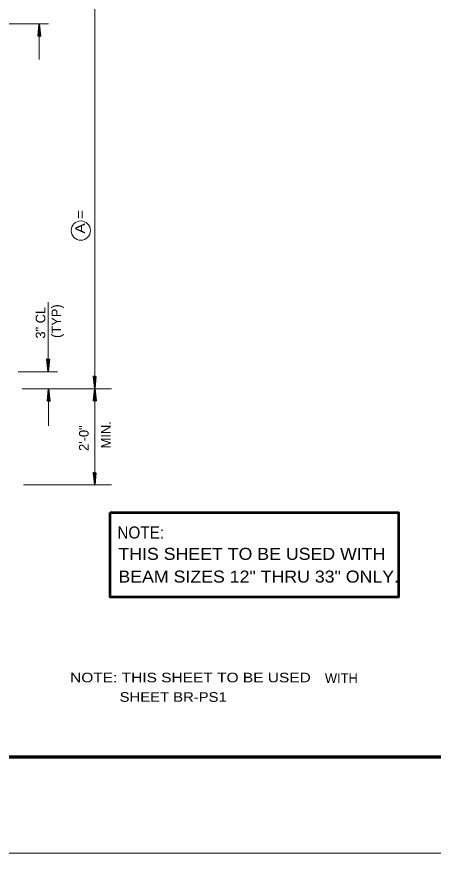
# Model space of a CAD drawing. Extents: x 14.14 to 17.34, y -1.61 to 0.38.
# Drawn here: x 15.839 to 16.199, y -1.605 to -0.881 of the extents above; entities that cross this region are included whole.
import ezdxf

# ---------------------------------------------------------------- set-up
doc = ezdxf.new("R2010")
doc.units = 0
doc.header["$LTSCALE"] = 0.0033
doc.layers.add('1', color=7, linetype='Continuous', lineweight=40)

msp = doc.modelspace()

# ---------------------------------------------------------------- linework, layer by layer
at = {"layer": '1', "lineweight": 13}
for p, q in [((15.906667, -1.285167), (15.906667, -0.869417)), ((15.743333, -0.887), (15.86675, -0.887)), ((15.85875, -0.917667), (15.85875, -0.896833)), ((15.866583, -1.18125), (15.866583, -1.127917)), ((15.840583, -1.188), (15.8745, -1.188)), ((15.844083, -1.202667), (15.92125, -1.202667)), ((15.866833, -1.234833), (15.866833, -1.214)), ((15.845083, -1.286), (15.92125, -1.286)), ((17.339333, -1.60475), (14.142583, -1.60475))]:
    msp.add_line(p, q, dxfattribs=at)
at = {"layer": '1', "lineweight": 35}
for p, q in [((15.85775, -0.89725), (15.858667, -0.889417)), ((15.85775, -0.89725), (15.858667, -0.889417)), ((15.857833, -0.89725), (15.858667, -0.889417)), ((15.857917, -0.89725), (15.85875, -0.889417)), ((15.857917, -0.89725), (15.858917, -0.889417)), ((15.859417, -0.897333), (15.858667, -0.89)), ((15.85875, -0.8975), (15.85875, -0.886917)), ((15.859583, -0.89725), (15.85875, -0.889917)), ((15.859667, -0.89725), (15.858917, -0.889917)), ((15.859833, -0.89725), (15.859, -0.889917)), ((15.865333, -1.177333), (15.866167, -1.184667)), ((15.8655, -1.177333), (15.86625, -1.184667)), ((15.865583, -1.177333), (15.866417, -1.184667)), ((15.86575, -1.17725), (15.8665, -1.184583)), ((15.86725, -1.177333), (15.86625, -1.185167)), ((15.866417, -1.177083), (15.866417, -1.187667)), ((15.86725, -1.177333), (15.866417, -1.185167)), ((15.867417, -1.177333), (15.8665, -1.185167)), ((15.867417, -1.177333), (15.8665, -1.185167)), ((15.867333, -1.177333), (15.8665, -1.185167)), ((15.905583, -1.19225), (15.906417, -1.199583)), ((15.90575, -1.19225), (15.9065, -1.199583)), ((15.905833, -1.19225), (15.906667, -1.199583)), ((15.906, -1.192167), (15.90675, -1.1995)), ((15.9075, -1.19225), (15.9065, -1.200083)), ((15.906667, -1.192), (15.906667, -1.202583)), ((15.9075, -1.19225), (15.906667, -1.200083)), ((15.907667, -1.19225), (15.90675, -1.200083)), ((15.907667, -1.19225), (15.90675, -1.200083)), ((15.907583, -1.19225), (15.90675, -1.200083)), ((15.865833, -1.213167), (15.86675, -1.205333)), ((15.865833, -1.213167), (15.86675, -1.205333)), ((15.865917, -1.213167), (15.86675, -1.205333)), ((15.866, -1.213167), (15.866833, -1.205333)), ((15.866, -1.213167), (15.867, -1.205333)), ((15.8675, -1.21325), (15.86675, -1.205917)), ((15.866833, -1.213417), (15.866833, -1.202833)), ((15.867667, -1.213167), (15.866833, -1.205833)), ((15.86775, -1.213167), (15.867, -1.205833)), ((15.867917, -1.213167), (15.867083, -1.205833)), ((15.905667, -1.213), (15.906583, -1.205167)), ((15.905667, -1.213), (15.906583, -1.205167)), ((15.90575, -1.213), (15.906583, -1.205167)), ((15.905833, -1.213), (15.906667, -1.205167)), ((15.905833, -1.213), (15.906833, -1.205167)), ((15.907333, -1.213083), (15.906583, -1.20575)), ((15.906667, -1.21325), (15.906667, -1.202667)), ((15.9075, -1.213), (15.906667, -1.205667)), ((15.907583, -1.213), (15.906833, -1.205667)), ((15.90775, -1.213), (15.906917, -1.205667)), ((15.905583, -1.275667), (15.906417, -1.283)), ((15.90575, -1.275667), (15.9065, -1.283)), ((15.905833, -1.275667), (15.906667, -1.283)), ((15.906, -1.275583), (15.90675, -1.282917)), ((15.9075, -1.275667), (15.9065, -1.2835)), ((15.906667, -1.275417), (15.906667, -1.286)), ((15.9075, -1.275667), (15.906667, -1.2835)), ((15.907667, -1.275667), (15.90675, -1.2835)), ((15.907667, -1.275667), (15.90675, -1.2835)), ((15.907583, -1.275667), (15.90675, -1.2835))]:
    msp.add_line(p, q, dxfattribs=at)
at = {"layer": '1', "lineweight": 70}
msp.add_line((14.309333, -1.521417), (17.256, -1.521417), dxfattribs=at)
at = {"layer": '1', "lineweight": 35}
for points in [[(15.857667, -0.8975), (15.85875, -0.886917), (15.859917, -0.8975), (15.85875, -0.896917)], [(15.858667, -0.89675), (15.858583, -0.892083), (15.858667, -0.892083), (15.858667, -0.893), (15.858583, -0.89675), (15.8585, -0.89375), (15.858417, -0.896917), (15.858333, -0.894667), (15.85825, -0.896917), (15.8585, -0.893417), (15.858667, -0.88875), (15.858917, -0.889667), (15.858917, -0.888417), (15.858917, -0.89675), (15.859083, -0.894333), (15.859083, -0.896917), (15.858667, -0.891583), (15.859333, -0.896917)], [(15.8675, -1.177083), (15.866417, -1.187667), (15.86525, -1.177083), (15.866417, -1.177667)], [(15.8665, -1.177833), (15.866583, -1.1825), (15.8665, -1.1825), (15.8665, -1.181583), (15.866583, -1.177833), (15.866667, -1.180833), (15.86675, -1.177667), (15.866833, -1.179917), (15.866917, -1.177667), (15.866667, -1.181167), (15.8665, -1.185833), (15.86625, -1.184917), (15.86625, -1.186167), (15.86625, -1.177833), (15.866083, -1.18025), (15.866083, -1.177667), (15.8665, -1.183), (15.865833, -1.177667)], [(15.90775, -1.192), (15.906667, -1.202583), (15.9055, -1.192), (15.906667, -1.192583)], [(15.90675, -1.19275), (15.906833, -1.197417), (15.90675, -1.197417), (15.90675, -1.1965), (15.906833, -1.19275), (15.906917, -1.19575), (15.907, -1.192583), (15.907083, -1.194833), (15.907167, -1.192583), (15.906917, -1.196083), (15.90675, -1.20075), (15.9065, -1.199833), (15.9065, -1.201083), (15.9065, -1.19275), (15.906333, -1.195167), (15.906333, -1.192583), (15.90675, -1.197917), (15.906083, -1.192583)], [(15.86575, -1.213417), (15.866833, -1.202833), (15.868, -1.213417), (15.866833, -1.212833)], [(15.86675, -1.212667), (15.866667, -1.208), (15.86675, -1.208), (15.86675, -1.208917), (15.866667, -1.212667), (15.866583, -1.209667), (15.8665, -1.212833), (15.866417, -1.210583), (15.866333, -1.212833), (15.866583, -1.209333), (15.86675, -1.204667), (15.867, -1.205583), (15.867, -1.204333), (15.867, -1.212667), (15.867167, -1.21025), (15.867167, -1.212833), (15.86675, -1.2075), (15.867417, -1.212833)], [(15.905583, -1.21325), (15.906667, -1.202667), (15.907833, -1.21325), (15.906667, -1.212667)], [(15.906583, -1.2125), (15.9065, -1.207833), (15.906583, -1.207833), (15.906583, -1.20875), (15.9065, -1.2125), (15.906417, -1.2095), (15.906333, -1.212667), (15.90625, -1.210417), (15.906167, -1.212667), (15.906417, -1.209167), (15.906583, -1.2045), (15.906833, -1.205417), (15.906833, -1.204167), (15.906833, -1.2125), (15.907, -1.210083), (15.907, -1.212667), (15.906583, -1.207333), (15.90725, -1.212667)], [(15.90775, -1.275417), (15.906667, -1.286), (15.9055, -1.275417), (15.906667, -1.276)], [(15.90675, -1.276167), (15.906833, -1.280833), (15.90675, -1.280833), (15.90675, -1.279917), (15.906833, -1.276167), (15.906917, -1.279167), (15.907, -1.276), (15.907083, -1.27825), (15.907167, -1.276), (15.906917, -1.2795), (15.90675, -1.284167), (15.9065, -1.28325), (15.9065, -1.2845), (15.9065, -1.276167), (15.906333, -1.278583), (15.906333, -1.276), (15.90675, -1.281333), (15.906083, -1.276)]]:
    msp.add_lwpolyline(points, close=True, dxfattribs=at)
for points in [[(15.858667, -0.89675), (15.857917, -0.897167), (15.858167, -0.896917), (15.8585, -0.89675), (15.858417, -0.8965), (15.858083, -0.896667), (15.858833, -0.896833), (15.859333, -0.897), (15.85975, -0.89725)], [(15.8665, -1.177833), (15.86725, -1.177417), (15.867, -1.177667), (15.866667, -1.177833), (15.86675, -1.178083), (15.867083, -1.177917), (15.866333, -1.17775), (15.865833, -1.177583), (15.865417, -1.177333)], [(15.90675, -1.19275), (15.9075, -1.192333), (15.90725, -1.192583), (15.906917, -1.19275), (15.907, -1.193), (15.907333, -1.192833), (15.906583, -1.192667), (15.906083, -1.1925), (15.905667, -1.19225)], [(15.86675, -1.212667), (15.866, -1.213083), (15.86625, -1.212833), (15.866583, -1.212667), (15.8665, -1.212417), (15.866167, -1.212583), (15.866917, -1.21275), (15.867417, -1.212917), (15.867833, -1.213167)], [(15.906583, -1.2125), (15.905833, -1.212917), (15.906083, -1.212667), (15.906417, -1.2125), (15.906333, -1.21225), (15.906, -1.212417), (15.90675, -1.212583), (15.90725, -1.21275), (15.907667, -1.213)], [(15.90675, -1.276167), (15.9075, -1.27575), (15.90725, -1.276), (15.906917, -1.276167), (15.907, -1.276417), (15.907333, -1.27625), (15.906583, -1.276083), (15.906083, -1.275917), (15.905667, -1.275667)]]:
    msp.add_lwpolyline(points, dxfattribs=at)
at = {"layer": '1'}
msp.add_lwpolyline([(14.309333, -1.521417), (16.671, -1.521417), (16.671, -1.196333), (17.256, -1.196333)], dxfattribs=at)
at = {"layer": '1', "lineweight": 53}
msp.add_lwpolyline([(15.920167, -1.309917), (16.169417, -1.309917), (16.169417, -1.383083), (15.920167, -1.383083)], close=True, dxfattribs=at)
at = {"layer": '1', "lineweight": 13}
msp.add_circle((15.894667, -1.065833), 0.008333, dxfattribs=at)

# ---------------------------------------------------------------- texts
at = {"layer": '1', "width": 1.2}
msp.add_text('A =      ', height=0.008334, rotation=90, dxfattribs=at).set_placement((15.89825, -1.068417))
at = {"layer": '1'}
for s, height, p in [('3" CL', 0.008334, (15.864, -1.159333)), ('(TYP)', 0.008334, (15.877667, -1.15875)), ('2\'-0"', 0.008333, (15.901417, -1.256583)), ('MIN.', 0.008334, (15.920583, -1.254333))]:
    msp.add_text(s, height=height, rotation=90, dxfattribs=at).set_placement(p)
for s, height, width, p in [('NOTE:', 0.01042, 0.95, (15.92625, -1.332333)), ('THIS SHEET TO BE USED WITH', 0.01042, 1.1, (15.927167, -1.350833)), ('BEAM SIZES 12" THRU 33" ONLY.', 0.01042, 1.1, (15.927167, -1.3705)), ('NOTE: THIS SHEET TO BE USED', 0.008334, 1.2, (15.885417, -1.456833)), ('SHEET BR-PS1', 0.008333, 1.15, (15.92825, -1.473667))]:
    msp.add_text(s, height=height, dxfattribs=dict(at, width=width)).set_placement(p)
msp.add_text('WITH', height=0.008333, dxfattribs=at).set_placement((16.105667, -1.457417))

doc.saveas('drawing.dxf')
